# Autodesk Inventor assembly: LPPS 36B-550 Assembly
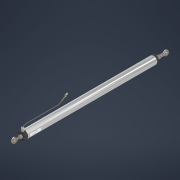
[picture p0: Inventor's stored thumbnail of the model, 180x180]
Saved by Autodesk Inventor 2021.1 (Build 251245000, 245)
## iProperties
Created: 2020-09
Part Number: LPPS 36B-550 Assembly
Document SubType Name: Assembly
Designer: J. Nielson
Author: J. Nielson
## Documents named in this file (3)
- C:\Users\Justin\Documents\CAD\The Sensor Connection\LPPS\LPPS-36B Series\3D\LPPS-36B-550\LPPS 36B-550 Assembly.iam
- C:\Users\Justin\Documents\CAD\The Sensor Connection\LPPS\LPPS-36B Series\3D\LPPS-36B-550\LPPS 36B-550 Shaft_Shrinkwrap.ipt
- C:\Users\Justin\Documents\CAD\The Sensor Connection\LPPS\LPPS-36B Series\3D\LPPS-36B-550\LPPS 36B-550_Shrinkwrap.ipt
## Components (2 placed, 2 different names)
1. LPPS 36B-550 Shaft_Shrinkwrap:1 — Mate:1, Angle:1, Cylindrical:1
2. LPPS 36B-550_Shrinkwrap:1 — Mate:1, Cylindrical:1
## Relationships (3: Mate 1, Angle 1, CylindricalJoint 1)
- Mate:1: LPPS 36B-550 Shaft_Shrinkwrap:1 ↔ LPPS 36B-550_Shrinkwrap:1
- Angle:1: LPPS 36B-550 Shaft_Shrinkwrap:1
- Cylindrical:1: LPPS 36B-550 Shaft_Shrinkwrap:1 ↔ LPPS 36B-550_Shrinkwrap:1
